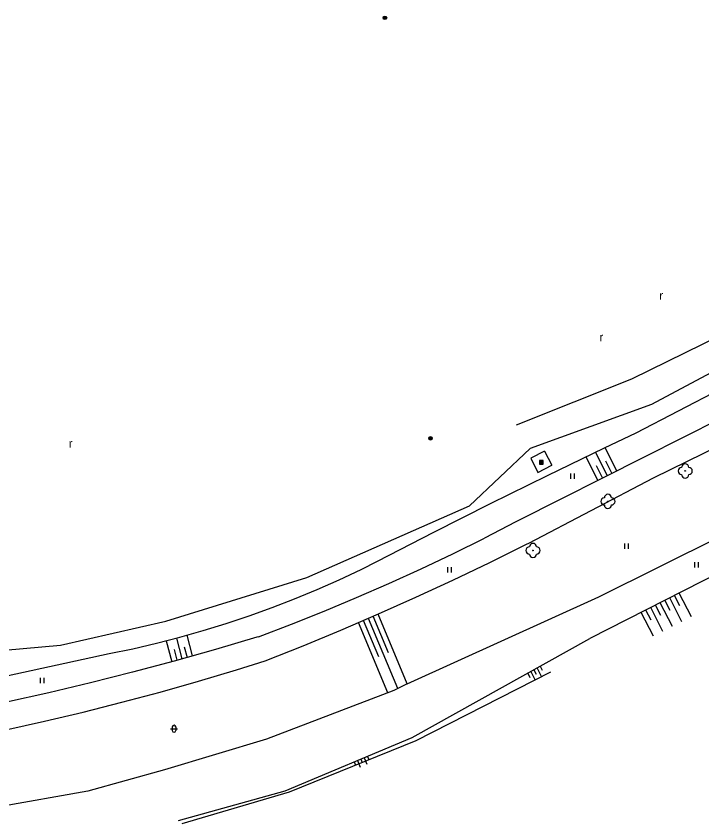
# Model space of a CAD drawing. Extents: x -538441 to -536770, y -1181008 to -1179809.
# Drawn here: x -537211.5 to -537115, y -1180705.6 to -1180592.8 of the extents above; entities that cross this region are included whole.
import ezdxf

# ---------------------------------------------------------------- set-up
doc = ezdxf.new("R2010")
doc.units = 0
for name, color, linetype in [('Vrstva 11', 7, 'Continuous'), ('Vrstva 14', 7, 'Continuous'), ('Vrstva 15', 7, 'Continuous'), ('Vrstva 22', 7, 'Continuous'), ('Vrstva 25', 7, 'Continuous'), ('Vrstva 36', 7, 'Continuous')]:
    doc.layers.add(name, color=color, linetype=linetype)

msp = doc.modelspace()

# ---------------------------------------------------------------- linework, layer by layer
at = {"layer": 'Vrstva 11'}
for p, q in [((-537124.82, -1180643.81), (-537105.92, -1180634.52)), ((-537104.73, -1180638.14), (-537122.09, -1180647.41)), ((-537141.06, -1180650.31), (-537124.82, -1180643.81)), ((-537122.09, -1180647.41), (-537139.14, -1180653.61)), ((-537147.67, -1180661.68), (-537139.14, -1180653.61)), ((-537137.122, -1180653.977), (-537136.102, -1180655.977)), ((-537170.55, -1180671.75), (-537147.67, -1180661.68)), ((-537190.41, -1180677.9), (-537170.55, -1180671.75)), ((-537205.24, -1180681.27), (-537190.41, -1180677.9)), ((-537213.1, -1180681.98), (-537205.24, -1180681.27))]:
    msp.add_line(p, q, dxfattribs=at)
msp.add_lwpolyline([(-537137.122, -1180653.977), (-537139.07, -1180654.97), (-537138.05, -1180656.97), (-537136.102, -1180655.977)], dxfattribs=at)
at = {"layer": 'Vrstva 14'}
for p, q in [((-537124.24, -1180651.416), (-537105.846, -1180641.843)), ((-537104.118, -1180645.243), (-537123.091, -1180654.845)), ((-537121.769, -1180657.733), (-537102.649, -1180648.308)), ((-537128.689, -1180653.527), (-537124.24, -1180651.416)), ((-537136.722, -1180657.408), (-537128.689, -1180653.527)), ((-537123.091, -1180654.845), (-537140.771, -1180663.739)), ((-537144.721, -1180661.361), (-537136.722, -1180657.408)), ((-537139.328, -1180666.912), (-537121.769, -1180657.733)), ((-537152.684, -1180665.386), (-537144.721, -1180661.361)), ((-537160.61, -1180669.481), (-537152.684, -1180665.386)), ((-537129.47, -1180674.5), (-537112.27, -1180665.93)), ((-537144.832, -1180669.65), (-537139.68, -1180667.09)), ((-537139.68, -1180667.09), (-537139.328, -1180666.912)), ((-537150.019, -1180672.138), (-537144.832, -1180669.65)), ((-537109.8, -1180669.69), (-537130.74, -1180680.36)), ((-537159.012, -1180672.604), (-537154.498, -1180670.548)), ((-537155.241, -1180674.554), (-537150.019, -1180672.138)), ((-537175.462, -1180675.996), (-537172.283, -1180674.765)), ((-537160.495, -1180676.896), (-537155.241, -1180674.554)), ((-537156.434, -1180686.719), (-537129.47, -1180674.5)), ((-537165.781, -1180679.166), (-537160.495, -1180676.896)), ((-537185.162, -1180679.235), (-537181.904, -1180678.231)), ((-537171.099, -1180681.362), (-537165.781, -1180679.166)), ((-537177.589, -1180680.157), (-537183.408, -1180681.874)), ((-537177.383, -1180680.094), (-537177.589, -1180680.157)), ((-537155.74, -1180694.29), (-537130.74, -1180680.36)), ((-537176.437, -1180683.48), (-537171.099, -1180681.362)), ((-537219.214, -1180687.006), (-537198.404, -1180682.478)), ((-537183.408, -1180681.874), (-537189.249, -1180683.513)), ((-537189.249, -1180683.513), (-537195.111, -1180685.076)), ((-537180.477, -1180684.745), (-537176.437, -1180683.48)), ((-537195.111, -1180685.076), (-537200.993, -1180686.561)), ((-537185.832, -1180686.347), (-537180.477, -1180684.745)), ((-537136.267, -1180685.083), (-537155.24, -1180694.76)), ((-537200.993, -1180686.561), (-537206.894, -1180687.968)), ((-537191.208, -1180687.873), (-537185.832, -1180686.347)), ((-537156.434, -1180686.719), (-537158.31, -1180687.64)), ((-537206.894, -1180687.968), (-537212.813, -1180689.298)), ((-537196.606, -1180689.321), (-537191.208, -1180687.873)), ((-537158.31, -1180687.64), (-537176.26, -1180694.52)), ((-537202.025, -1180690.692), (-537196.606, -1180689.321)), ((-537207.462, -1180691.985), (-537202.025, -1180690.692)), ((-537212.917, -1180693.201), (-537207.462, -1180691.985)), ((-537176.26, -1180694.52), (-537190.61, -1180698.8)), ((-537173.61, -1180701.76), (-537155.74, -1180694.29)), ((-537155.24, -1180694.76), (-537173.04, -1180701.97)), ((-537190.61, -1180698.8), (-537201.4, -1180701.83)), ((-537201.4, -1180701.83), (-537221.27, -1180705.36)), ((-537188.63, -1180705.94), (-537173.61, -1180701.76)), ((-537173.04, -1180701.97), (-537188.18, -1180706.42))]:
    msp.add_line(p, q, dxfattribs=at)
for points in [[(-537140.771, -1180663.739), (-537141.163, -1180663.945), (-537145.572, -1180666.218)], [(-537154.498, -1180670.548), (-537150.018, -1180668.419), (-537145.572, -1180666.218)], [(-537166.014, -1180672.082), (-537162.929, -1180670.631), (-537160.61, -1180669.481)], [(-537172.283, -1180674.765), (-537169.133, -1180673.46), (-537166.014, -1180672.082)], [(-537168.137, -1180676.497), (-537163.559, -1180674.588), (-537159.012, -1180672.604)], [(-537181.904, -1180678.231), (-537178.67, -1180677.151), (-537175.462, -1180675.996)], [(-537177.383, -1180680.094), (-537172.745, -1180678.333), (-537168.137, -1180676.497)], [(-537191.745, -1180681.011), (-537188.443, -1180680.162), (-537185.162, -1180679.235)], [(-537198.404, -1180682.478), (-537195.065, -1180681.784), (-537191.745, -1180681.011)]]:
    msp.add_lwpolyline(points, dxfattribs=at)
at = {"layer": 'Vrstva 15'}
for p, q in [((-537128.617, -1180653.493), (-537126.958, -1180656.79)), ((-537129.97, -1180654.14), (-537128.298, -1180657.464)), ((-537131.323, -1180654.79), (-537129.638, -1180658.139)), ((-537128.527, -1180655.34), (-537127.628, -1180657.127)), ((-537129.867, -1180656.014), (-537128.968, -1180657.801)), ((-537119.436, -1180676.425), (-537120.175, -1180674.976)), ((-537117.799, -1180677.986), (-537119.507, -1180674.635)), ((-537118.1, -1180675.744), (-537118.839, -1180674.295)), ((-537116.462, -1180677.305), (-537118.17, -1180673.954)), ((-537120.472, -1180679.349), (-537122.18, -1180675.998)), ((-537120.772, -1180677.106), (-537121.511, -1180675.657)), ((-537119.135, -1180678.668), (-537120.843, -1180675.317)), ((-537159.069, -1180682.36), (-537161.222, -1180677.214)), ((-537156.434, -1180686.719), (-537160.534, -1180676.914)), ((-537121.808, -1180680.03), (-537123.516, -1180676.679)), ((-537122.109, -1180677.788), (-537122.848, -1180676.338)), ((-537159.163, -1180687.967), (-537163.287, -1180678.106)), ((-537160.453, -1180682.939), (-537162.598, -1180677.81)), ((-537157.783, -1180687.381), (-537161.91, -1180677.512)), ((-537188.916, -1180680.288), (-537188.137, -1180683.207)), ((-537187.468, -1180679.895), (-537186.691, -1180682.806)), ((-537190.367, -1180680.667), (-537189.583, -1180683.605)), ((-537187.808, -1180681.529), (-537187.414, -1180683.007)), ((-537189.258, -1180681.916), (-537188.86, -1180683.407)), ((-537139.046, -1180684.988), (-537138.445, -1180686.194)), ((-537138.61, -1180684.745), (-537138.296, -1180685.373)), ((-537138.173, -1180684.502), (-537137.555, -1180685.74)), ((-537137.735, -1180684.258), (-537137.461, -1180684.807)), ((-537139.483, -1180685.232), (-537139.184, -1180685.834)), ((-537163.429, -1180697.504), (-537163.044, -1180698.426)), ((-537162.968, -1180697.311), (-537162.775, -1180697.772)), ((-537162.507, -1180697.118), (-537162.121, -1180698.041)), ((-537162.045, -1180696.925), (-537161.853, -1180697.387)), ((-537163.891, -1180697.697), (-537163.698, -1180698.158))]:
    msp.add_line(p, q, dxfattribs=at)
at = {"layer": 'Vrstva 22'}
for centre in [(-537117.326, -1180656.776), (-537128.202, -1180661.062), (-537138.748, -1180667.962)]:
    msp.add_circle(centre, 0.05, dxfattribs=at)
for centre, start, end in [((-537117.326, -1180656.276), 0, 180), ((-537117.826, -1180656.776), 90, 270), ((-537116.826, -1180656.776), 270, 90), ((-537117.326, -1180657.276), 180, 0), ((-537128.202, -1180660.562), 0, 180), ((-537128.702, -1180661.062), 90, 270), ((-537127.702, -1180661.062), 270, 90), ((-537128.202, -1180661.562), 180, 0), ((-537138.748, -1180667.462), 0, 180), ((-537139.248, -1180667.962), 90, 270), ((-537138.248, -1180667.962), 270, 90), ((-537138.748, -1180668.462), 180, 0)]:
    msp.add_arc(centre, 0.5, start, end, dxfattribs=at)
at = {"layer": 'Vrstva 25'}
for points in [[(-537137.83, -1180655.8), (-537137.33, -1180655.8), (-537137.33, -1180655.3), (-537137.83, -1180655.3)], [(-537137.78, -1180655.75), (-537137.38, -1180655.75), (-537137.38, -1180655.35), (-537137.78, -1180655.35)], [(-537137.73, -1180655.7), (-537137.43, -1180655.7), (-537137.43, -1180655.4), (-537137.73, -1180655.4)], [(-537137.68, -1180655.65), (-537137.48, -1180655.65), (-537137.48, -1180655.45), (-537137.68, -1180655.45)], [(-537137.63, -1180655.6), (-537137.53, -1180655.6), (-537137.53, -1180655.5), (-537137.63, -1180655.5)]]:
    msp.add_lwpolyline(points, close=True, dxfattribs=at)
for centre, radius in [((-537159.58, -1180593.03), 0.25), ((-537159.58, -1180593.03), 0.2), ((-537159.58, -1180593.03), 0.15), ((-537159.58, -1180593.03), 0.1), ((-537159.58, -1180593.03), 0.05), ((-537153.17, -1180652.18), 0.25), ((-537153.17, -1180652.18), 0.2), ((-537153.17, -1180652.18), 0.15), ((-537153.17, -1180652.18), 0.1), ((-537153.17, -1180652.18), 0.05)]:
    msp.add_circle(centre, radius, dxfattribs=at)
at = {"layer": 'Vrstva 36'}
for p, q in [((-537133.413, -1180657.862), (-537133.413, -1180657.112)), ((-537132.913, -1180657.862), (-537132.913, -1180657.112)), ((-537125.822, -1180667.753), (-537125.822, -1180667.003)), ((-537125.322, -1180667.753), (-537125.322, -1180667.003)), ((-537150.707, -1180671.079), (-537150.707, -1180670.329)), ((-537150.207, -1180671.079), (-537150.207, -1180670.329)), ((-537115.976, -1180670.367), (-537115.976, -1180669.617)), ((-537115.476, -1180670.367), (-537115.476, -1180669.617)), ((-537208.049, -1180686.624), (-537208.049, -1180685.874)), ((-537207.549, -1180686.624), (-537207.549, -1180685.874)), ((-537189.758, -1180693.043), (-537188.758, -1180693.043)), ((-537189.508, -1180692.793), (-537189.508, -1180693.293)), ((-537189.008, -1180692.793), (-537189.008, -1180693.293))]:
    msp.add_line(p, q, dxfattribs=at)
for centre, start, end in [((-537189.258, -1180692.793), 0, 180), ((-537189.258, -1180693.293), 180, 0)]:
    msp.add_arc(centre, 0.25, start, end, dxfattribs=at)

# ---------------------------------------------------------------- texts
for p in [(-537120.969, -1180632.695), (-537129.388, -1180638.553), (-537204.072, -1180653.49)]:
    msp.add_text('r', height=1.2, dxfattribs=at).set_placement(p)

doc.saveas('drawing.dxf')
